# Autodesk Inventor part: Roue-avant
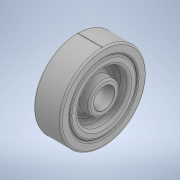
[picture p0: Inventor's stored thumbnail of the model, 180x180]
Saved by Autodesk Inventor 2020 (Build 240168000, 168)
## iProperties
Created: 1900-01
Part Number: Roue-avant
Material: Générique
Document SubType Name: Modeling
Designer: bruno
Density: 1 g/cm^3
Appearance: Par défaut
Mass: 191.833 g
Surface Area: 346.706 cm^2
Volume: 191.833 cm^3
Author: bruno
Revision Number: ANYUNSPECIFIED
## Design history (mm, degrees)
feature "Base1"
node "Plan de construction2"
sketch "Esquisse1"
  geometry: L1 (-18.078, -29.73)-(20.996, -29.73); L2 (20.996, -29.73)-(20.996, -36); L3 (14, -36)-(-14, -36); L4 (-18.078, -36)-(-18.078, -29.73); L5 (16.2, -74)-(-16.2, -74) reference; L6 (0, -74)-(0, -98); L7 (16.2, -98)-(-16.2, -98) reference; L8 (0, -86)-(16.2, -86); L9 (16.2, -74)-(16.2, -98) reference; L10 (-16, -39.005)-(-16, -132.995) reference; L11 (16, -39.005)-(16, -132.995) reference; L12 (-16, -39.005)-(-16, -38); L13 (16, -39.005)-(16, -38); L14 (-16, -39.005)-(16, -39.005); A1 r 2 centre (-14, -38) between (-14, -36) and (-16, -38); A2 r 2 centre (14, -38) between (16, -38) and (14, -36); 1 further point
  constraints: 18 end point, 4 midpoint, 4 point on circle, 4 tangent, 3 parallel, 2 centre point, 2 horizontal, 2 perpendicular, 2 point on line, 1 equal radius
  dimensions: "d1" = 50 distance between parallel lines of L3 L8; "d2" = 2 radius of A1 (derived)
revolve "Révolution1" sketch "Esquisse1" stored, may be unused: angle "d3" = 90 deg
sketch "Esquisse2"
  geometry: L1 (0, 0)-(0, 50); C1 r 0.25 at (0, 50); C2 r 15.667 at (0, 0) reference; 2 further points
  constraints: 2 end point, 1 centre point, 1 coincident, 1 vertical, 1 vertical alignment, 1 other
  dimensions: "d6" = 0.5 diameter of C1
extrude "Extrusion1" cut sketch "Esquisse2" distance "d4" = 100; taper "d5" = 0 deg
node "Solide1"
